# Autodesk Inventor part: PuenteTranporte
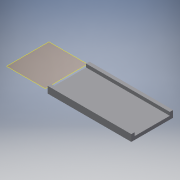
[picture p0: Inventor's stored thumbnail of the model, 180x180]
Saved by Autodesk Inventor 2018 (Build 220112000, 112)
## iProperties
Created: 2021-01
Part Number: PuenteTranporte
Material: Genérico
Document SubType Name: Modeling
Designer: ATOUZA
Density: 1 g/cm^3
Appearance: Valor por defecto
Author: ATOUZA
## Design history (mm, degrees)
node "Plano de trabajo1"
sketch "Boceto1"
  geometry: L1 (-21, -21)-(19, -21) reference; L2 (21, -23)-(21, 23) reference; L3 (19, 21)-(-21, 21) reference; L4 (-21, 21)-(-21, -21) reference; L5 (25.673, -21)-(125.673, -21); L6 (125.673, -21)-(125.673, 21); L7 (125.673, 21)-(25.673, 21); L8 (25.673, 21)-(25.673, -21); C1 r 3 at (-10.25, 12.5) reference; C2 r 3 at (7.75, 12.5) reference; C3 r 3 at (7.75, -12.5) reference; C4 r 3 at (-10.25, -12.5) reference; A1 r 2 centre (19, -23) between (21, -23) and (19, -21) reference; A2 r 2 centre (19, 23) between (19, 21) and (21, 23) reference; 1 further point
  constraints: 8 end point, 2 parallel, 1 horizontal, 1 perpendicular
  dimensions: "d0" = 100 distance of L7.end L6.end
extrude "Extrusión1" new body sketch "Boceto1" distance "d1" = 4; taper "d2" = 0 deg
sketch "Boceto2"
  geometry: L1 (100, 4)-(0, 4) reference; L2 (100, 4)-(0, 4); L3 (0, 4)-(0, -4); L4 (0, -4)-(100, -4); L5 (100, -4)-(100, 4); 1 further point
  constraints: 8 end point, 3 equal length, 1 perpendicular
  dimensions: "d3" = 8 distance of L3.end L1.end
extrude "Extrusión2" join sketch "Boceto2" distance "d4" = 4; taper "d5" = 0 deg
mirror "Simetría1"
node "Sólido1"
node "Referencia2"
